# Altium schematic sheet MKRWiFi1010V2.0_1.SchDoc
size A3; Author: Arturo Guadalupi; SheetNumber: 2; SheetTotal: 2; RevAuthor: Francesca Cenna
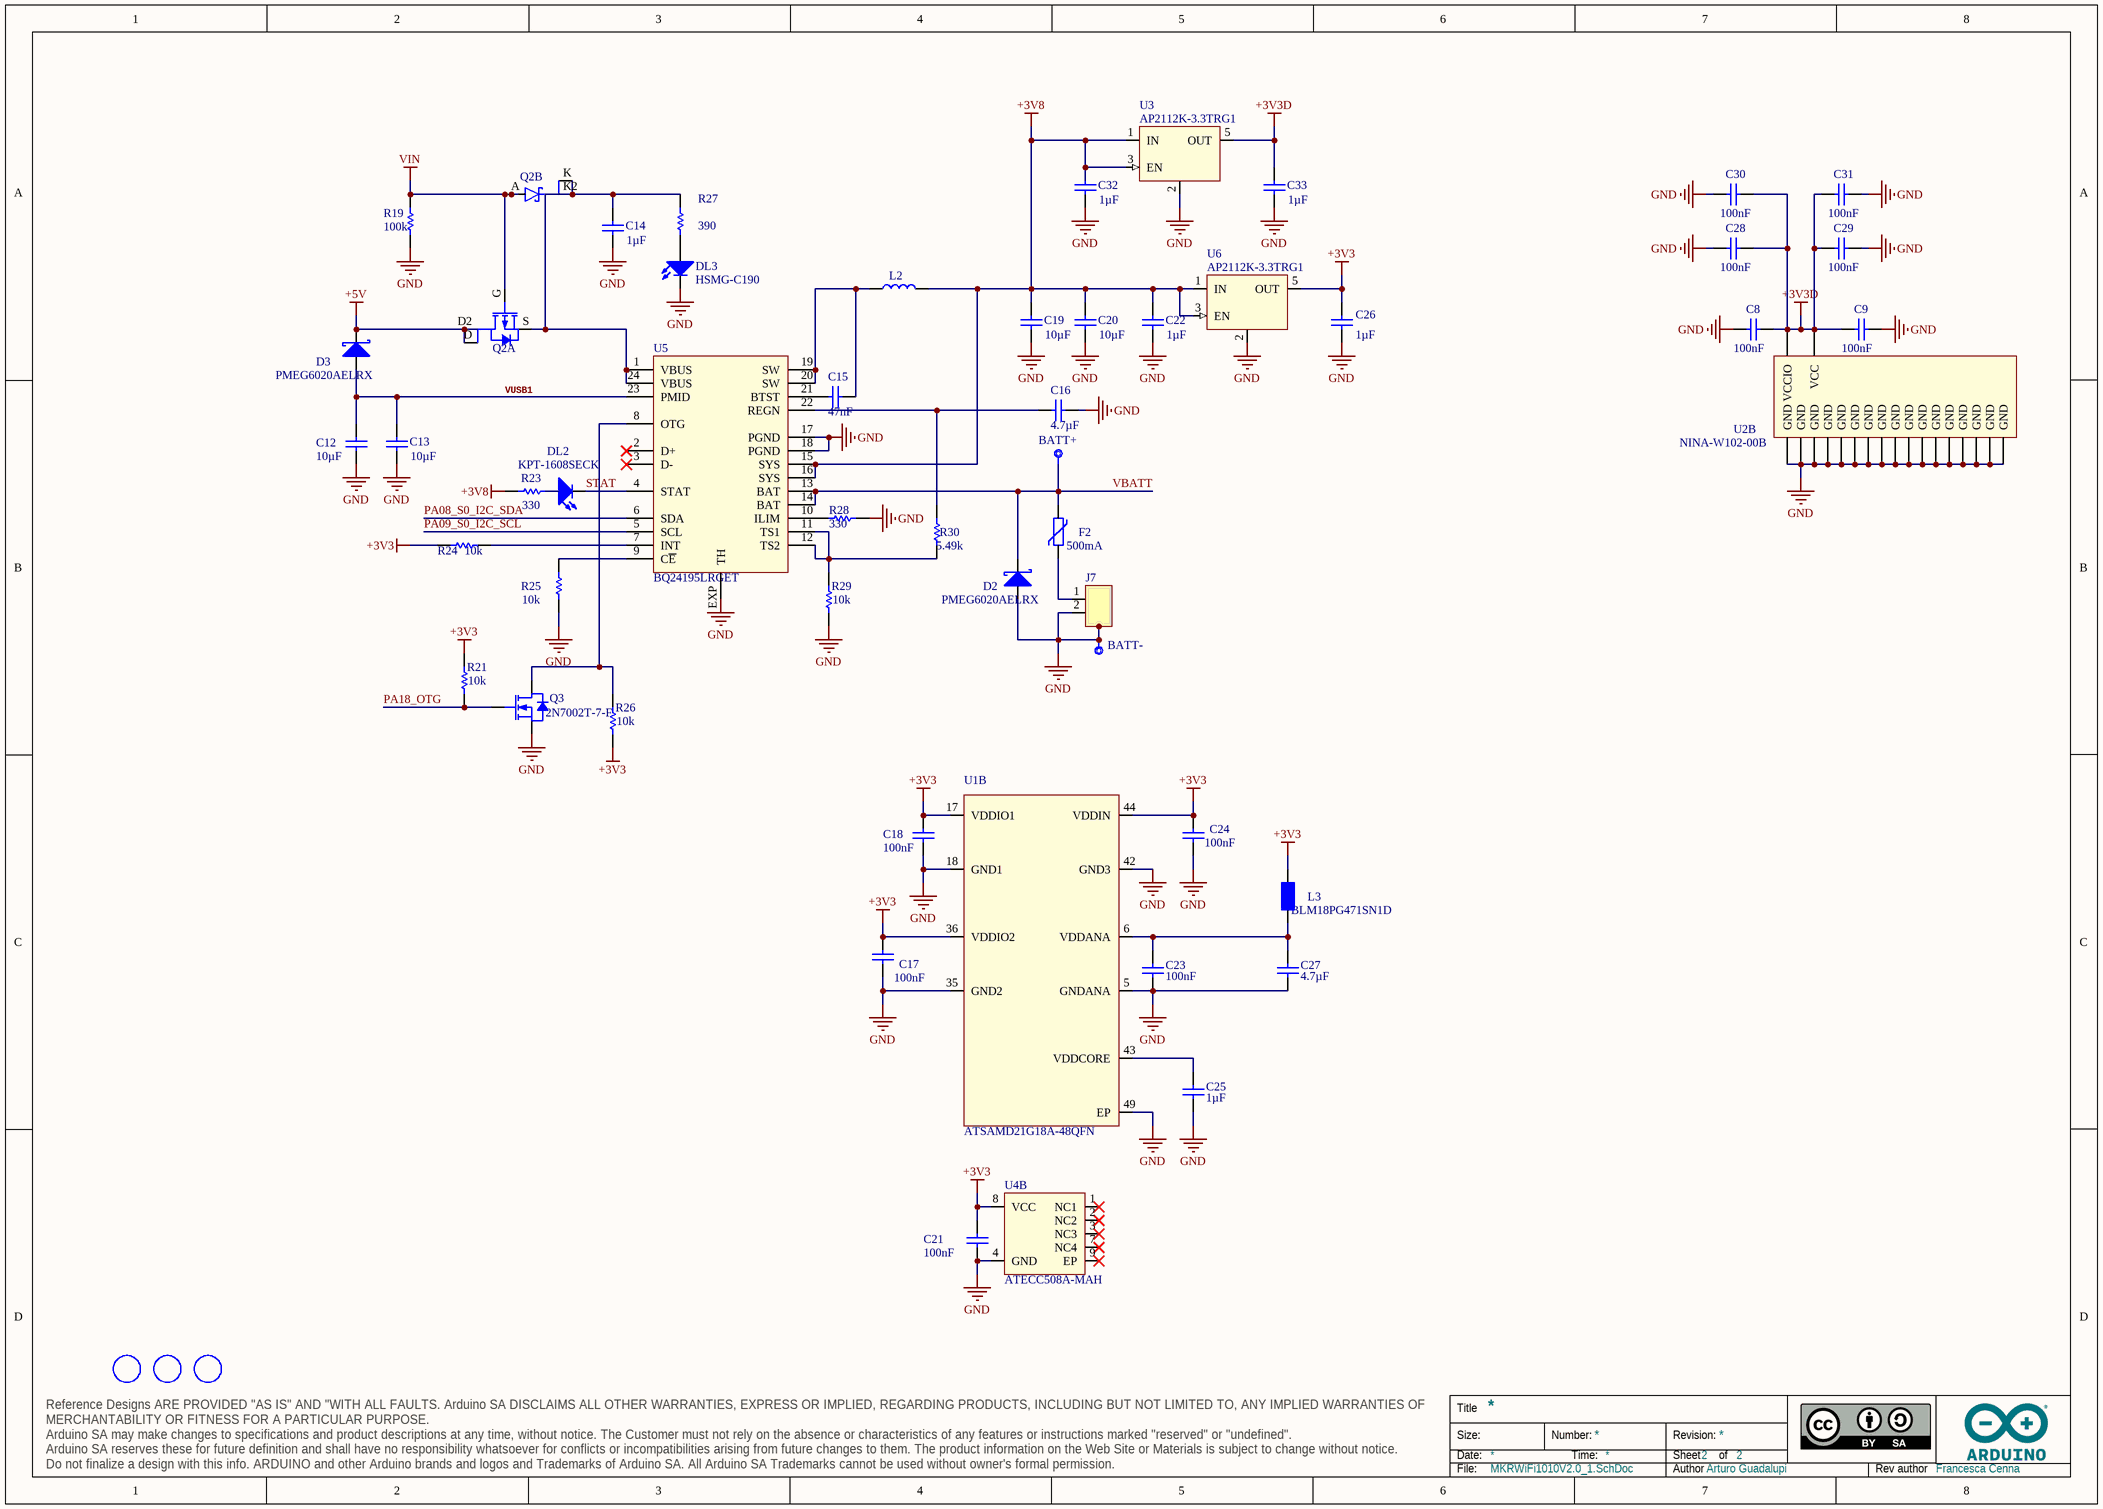
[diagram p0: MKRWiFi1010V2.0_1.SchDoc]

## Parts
BATT+  CMP-018-0005-A.3  [TP-1.00MM]  (value not drawn)  (no BOM)
BATT-  CMP-018-0005-A.3  [TP-1.00MM]  (value not drawn)  (no BOM)
C8  value 100nF  [CAP-0402]  (hidden comment: C0402C104K8PACTU)
C9  value 100nF  [CAP-0402]  (hidden comment: C0402C104K8PACTU)
C12  value 10µF  [CAP-0603]  (hidden comment: GRM188R61E106MA73J)
C13  value 10µF  [CAP-0603]  (hidden comment: GRM188R61E106MA73J)
C14  value 1µF  [CAP-0402]  (hidden comment: C0402C105K4PACTU)
C15  value 47nF  [CAP-0402]  (hidden comment: GRM155R61H473KE14D)
C16  value 4.7µF  [CAP-0402]  (hidden comment: GRM155R60J475ME47D)
C17  value 100nF  [CAP-0402]  (hidden comment: C0402C104K8PACTU)
C18  value 100nF  [CAP-0402]  (hidden comment: C0402C104K8PACTU)
C19  value 10µF  [CAP-0603]  (hidden comment: GRM188R61E106MA73J)
C20  value 10µF  [CAP-0603]  (hidden comment: GRM188R61E106MA73J)
C21  value 100nF  [CAP-0402]  (hidden comment: C0402C104K8PACTU)
C22  value 1µF  [CAP-0402]  (hidden comment: C0402C105K4PACTU)
C23  value 100nF  [CAP-0402]  (hidden comment: C0402C104K8PACTU)
C24  value 100nF  [CAP-0402]  (hidden comment: C0402C104K8PACTU)
C25  value 1µF  [CAP-0402]  (hidden comment: C0402C105K4PACTU)
C26  value 1µF  [CAP-0402]  (hidden comment: C0402C105K4PACTU)
C27  value 4.7µF  [CAP-0603]  (hidden comment: GRM188R6YA475KE15D)
C28  value 100nF  [CAP-0402]  (hidden comment: C0402C104K8PACTU)
C29  value 100nF  [CAP-0402]  (hidden comment: C0402C104K8PACTU)
C30  value 100nF  [CAP-0603]  (hidden comment: 06035G104ZAT4A)
C31  value 100nF  [CAP-0603]  (hidden comment: 06035G104ZAT4A)
C32  value 1µF  [CAP-0402]  (hidden comment: C0402C105K4PACTU)
C33  value 1µF  [CAP-0402]  (hidden comment: C0402C105K4PACTU)
D2  PMEG6020AELRX  [SOD123-1]
D3  PMEG6020AELRX  [SOD123-1]
DL2  KPT-1608SECK  [LEDC1608X80N-AK]
DL3  HSMG-C190  [LEDC1608X80N-AK]
F2  Current: 500mA  [0603]  (hidden comment: MF-FSMF050X-2)
FD1  Fiducial mark 1.5mm  [FIDUCIAL-1.5]  (value not drawn)  (no BOM)
FD2  Fiducial mark 1.5mm  [FIDUCIAL-1.5]  (value not drawn)  (no BOM)
FD3  Fiducial mark 1.5mm  [FIDUCIAL-1.5]  (value not drawn)  (no BOM)
J7  19TW-108  [JST-S2B-PH-SM4-TB]  (value not drawn)
L2  SRP4020TA-2R2M  [SRP4020]  (value not drawn)
L3  BLM18PG471SN1D  [L-0603]
Q2  SIA817EDJ-T1-GE3  [SON65P205X205X75-8N-MWSD]  (value not drawn)  (parts A,B of 2)
Q3  2N7002T-7-F  [SOT523]
R19  value 100k  [RES-0402]  (hidden comment: CRCW0402100KFKEDC)
R21  value 10k  [RES-0402]  (hidden comment: CRCW040210K0FKED)
R23  value 330  [RES-0402]  (hidden comment: CRCW0402330RJNED)
R24  value 10k  [RES-0402]  (hidden comment: CRCW040210K0FKED)
R25  value 10k  [RES-0402]  (hidden comment: CRCW040210K0FKED)
R26  value 10k  [RES-0402]  (hidden comment: CRCW040210K0FKED)
R27  value 390  [RES-0402]  (hidden comment: RC0402FR-07390RL)
R28  value 330  [RES-0402]  (hidden comment: CRCW0402330RJNED)
R29  value 10k  [RES-0402]  (hidden comment: CRCW040210K0FKED)
R30  value 5.49k  [RES-0402]  (hidden comment: CRCW04025K49FKED)
U1  Part Number: ATSAMD21G18A-48QFN  [QFN48]  (hidden comment: ATSAMD21G18A-48QFN-A.5)  (part B of 2)
U2  NINA-W102-00B  [NINA-W102]  (part B of 2)
U3  Part Number: AP2112K-3.3TRG1  [SOT25]  (hidden comment: AP2112K-3.3TRG1-A.6)
U4  ATECC508A-MAH  [UDFN8]  (part B of 2)
U5  Part Number: BQ24195LRGET  [VQFN24]  (hidden comment: BQ24195LRGET-A.4)
U6  Part Number: AP2112K-3.3TRG1  [SOT25]  (hidden comment: AP2112K-3.3TRG1-A.6)

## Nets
+3V3: C17.2 C18.2 C21.2 C24.2 C26.2 L3.1 R21.1 R24.1 R26.1 U1.17(VDDIO1) U1.36(VDDIO2) U1.44(VDDIN) U4.8(VCC) U6.5(OUT)
+3V3D: C8.2 C9.1 C28.1 C29.2 C30.1 C31.2 C33.2 U2.9(VCCIO) U2.10(VCC) U3.5(OUT)
+3V8: C19.2 C20.2 C22.2 C32.2 L2.2 R23.2 U3.1(IN) U3.3(EN) U5.15(SYS) U5.16(SYS) U6.1(IN) U6.3(EN)
+5V: D3.C Q2.D Q2.D2
GND: BATT-.X C8.1 C9.2 C12.1 C13.1 C14.2 C16.2 C17.1 C18.1 C19.1 C20.1 C21.1 C22.1 C23.2 C24.1 C25.2 C26.1 C27.2 C28.2 C29.1 C30.2 C31.1 C32.1 C33.1 D2.A DL3.C J7.2 J7.3(SH) J7.4(SH) Q3.S R19.1 R25.1 R28.2 R29.1 U1.5(GNDANA) U1.18(GND1) U1.35(GND2) U1.42(GND3) U1.49(EP) U2.6(GND) U2.12(GND) U2.14(GND) U2.26(GND) U2.30(GND) U2.GND1(GND) U2.GND2(GND) U2.GND3(GND) U2.GND4(GND) U2.GND5(GND) U2.GND6(GND) U2.GND7(GND) U2.GND8(GND) U2.GND9(GND) U2.GND10(GND) U2.GND11(GND) U2.GND12(GND) U3.2(GND/ADJ) U4.4(GND) U5.17(PGND) U5.18(PGND) U5.EXP(TH) U6.2(GND/ADJ)
VIN: Q2.A Q2.G R19.2
PA08_S0_I2C_SDA: U5.6(SDA)
PA09_S0_I2C_SCL: U5.5(SCL)
PA18_OTG: Q3.G R21.2
STAT: DL2.C U5.4(STAT)
VBATT: BATT+.X D2.C F2.2 U5.13(BAT) U5.14(BAT)
VUSB1: C12.2 C13.2 D3.A U5.23(PMID)
NetC14_1: C14.1 Q2.K Q2.K2 Q2.S R27.2 U5.1(VBUS) U5.24(VBUS)
NetC15_1: C15.1 U5.21(BTST)
NetC15_2: C15.2 L2.1 U5.19(SW) U5.20(SW)
NetC16_1: C16.1 R30.1 U5.22(REGN)
NetC23_1: C23.1 C27.1 L3.2 U1.6(VDDANA)
NetC25_1: C25.1 U1.43(VDDCORE)
NetDL2_A: DL2.A R23.1
NetDL3_A: DL3.A R27.1
NetF2_1: F2.1 J7.1
NetQ3_D: Q3.D R26.2 U5.8(OTG)
NetR24_2: R24.2 U5.7(INT)
NetR25_2: R25.2 U5.9(C~{E})
NetR28_1: R28.1 U5.10(ILIM)
NetR29_2: R29.2 R30.2 U5.11(TS1) U5.12(TS2)

Not connected (* = marked no-connect by the designer): U4 1(NC1)* 2(NC2)* 3(NC3)* 7(NC4)* 9(EP)*; U5 2(D+)* 3(D-)*

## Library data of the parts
BATT+ BATT- = UT0013-A.1: Test point 1.00mm
C8 C9 C17 C18 C21 C23 C24 C28 C29 = C0011-A.3: CAP CHIP 0402 100nf 10V X5R 10%; Manufacturer: KEMET; Code Arduino: 0132
C12 C13 C19 C20 = C0047-A.6: CAP CHIP 0603 10uF 25V X5R 20%; Manufacturer: Murata; Part Number: C1608X5R1A226MT000N; Code Arduino: 2213
C14 C22 C25 C26 C32 C33 = C0018-A.3: CAP CHIP 0402 1uF 16V X5R 10%; Manufacturer: KEMET; Code Arduino: 0133
C15 = C0036-A.3: CAP CHIP 0402 47nF 50V X5R 10%; Manufacturer: Murata; Code Arduino: 2216
C16 = C0037-A.3: CAP CHIP 0402 4.7uF 6V3 X5R 20%; Manufacturer: Murata; Code Arduino: 0833; Voltage: 6.3V
C27 = C0055-A.3: CAP CHIP 0603 4.7uF 35V X5R 10%; Manufacturer: Murata; Code Arduino: 0458
C30 C31 = C0041-A.3: CAP CHIP 0603 100nF 50V Y5V -20/+80%; Manufacturer: AVX; Code Arduino: 0015; Tolerance: '-20%/+80%
D2 D3 = D0026-A.2: DIODE SCHOTTKY SMD 1A 40V SOD123FL; Manufacturer: Nexperia; Code Arduino: 2208
DL2 = L0006-A.2: LED SMD 0603 ORANGE601 250mcd 120^; Manufacturer: Kingbright; Code Arduino: 2207
DL3 = L0009-A.2: LED SMD 0603 GREEN/568 15mcd 120^; Manufacturer: Broadcom; Code Arduino: 2204
F2 = P0000-A.2: PTC SMD 0603 RESET FUSE 6V 0.5A; Manufacturer: Bourns; Code Arduino: 2217; Voltage: 40V
FD1-FD3 = UT0000-A.1
J7 = J0060-A.1: CONN p2mm SMD M/90 2v S2B-PH..; Code Arduino: 2355
L2 = I0017-A.3: IND FIXED 2.2UH 4A 61 MOHM SMD; Manufacturer: Bourns; Code Arduino: 2218
L3 = I0006-A.2: FERRITE SMD 0603 470R 1A 0.2R; Manufacturer: Murata; Code Arduino: 2200; Test Frequency: 100MHz; DC Resistance (DCR): 200mR; Tolerance: 25%; Impedance: 470µH
Q2 = T0010-A.1: MOSFET P-CH 30V 4,5A 65mR SC70-6; Code Arduino: 2220; Device Type: Mosfet P-CH SMD
Q3 = T0003-A.1: MOSFET N-CH 60V 115mA SOT523; Manufacturer: Diodes Inc.; Code Arduino: 2368; Device Type: Mosfet N-CH SMD
R19 = R0001-A.3: RES CHIP 0402 100K 1% 1/16W; Manufacturer: Vishay; Code Arduino: 0134; Power: 63mW
R21 R24-R26 R29 = R0003-A.3: RES CHIP 0402 10K 1% 1/16W; Manufacturer: Vishay; Code Arduino: 0136; Power: 63mW
R23 R28 = R0017-A.3: RES CHIP 0402 330R 5% 1/16W; Manufacturer: Vishay; Code Arduino: 2229; Power: 63mW
R27 = R0012-A.3: RES CHIP 0402 390R 1% 1/16W; Manufacturer: Yageo; Code Arduino: 2195; Power: 63mW
R30 = R0014-A.3: RES CHIP 0402 5K49 1% 1/16W; Manufacturer: Vishay; Code Arduino: 2197; Power: 63mW
U1 = U0041-A.2: IC ATSAMD21G18A-48QFN; Manufacturer: Microchip
U2 = M0002-A.2: MODULE ESP32 WiFi/BLE; Manufacturer: UBlox
U3 U6 = U0027-A.2: IC V-REG LDO 3V3 600mA +En  SOT25; Manufacturer: Diodes Inc; Code Arduino: 2199
U4 = U0033-A.2: IC CRYPTO PROC.256b  UDFN8; Manufacturer: Microchip; Code Arduino: ATECC508A-MAHDA-T8-UDFN
U5 = U0044-A.3: IC BATT.CHRG.CTRL. VQFN24; Manufacturer: Texas Instruments; Code Arduino: 2201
